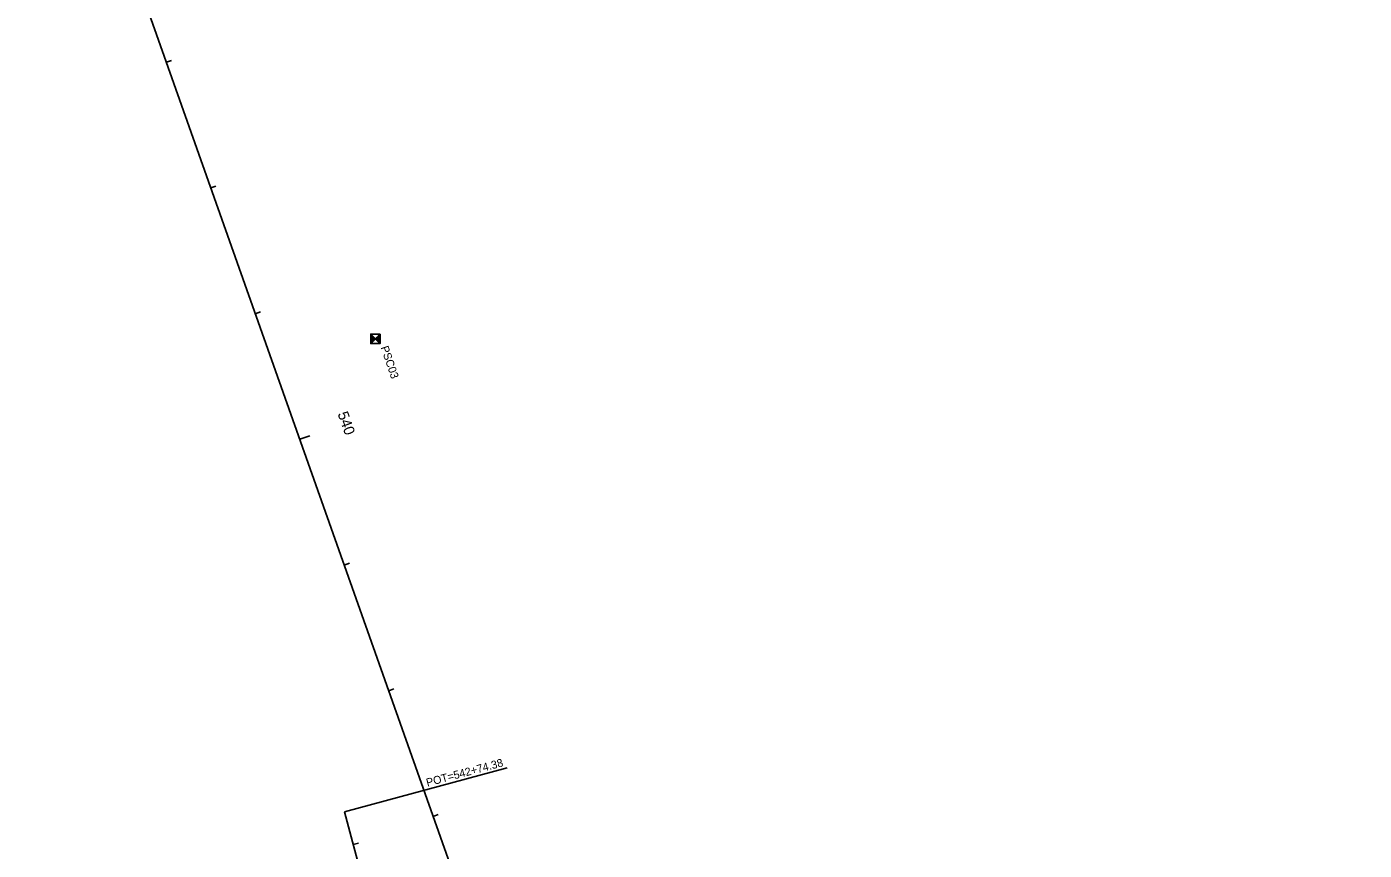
# Model space of a CAD drawing. Extents: x 2004390 to 2008791, y 1133870 to 1140084.
# Drawn here: x 2005036 to 2006039, y 1138747 to 1139364 of the extents above; entities that cross this region are included whole.
import ezdxf

# ---------------------------------------------------------------- set-up
doc = ezdxf.new("R2010")
doc.units = 0
for name, color, linetype in [('RD_HC_Cl', 7, 'Continuous'), ('RD_HC_Data', 7, 'Continuous'), ('RD_HC_Data_Tic', 7, 'Continuous'), ('RD_HC_Survey', 7, 'Continuous'), ('RD_HC_Survey_txCode', 7, 'Continuous'), ('RD_HC_TX_Sta50', 7, 'Continuous')]:
    doc.layers.add(name, color=color, linetype=linetype)

msp = doc.modelspace()

# ---------------------------------------------------------------- linework, layer by layer
at = {"layer": 'RD_HC_Cl'}
for p, q in [((2005036.1, 1139633.5), (2007075.2, 1133869.8)), ((2005274.3, 1138775.6), (2005410.4, 1138267.8))]:
    msp.add_line(p, q, dxfattribs=at)
at = {"layer": 'RD_HC_Data'}
msp.add_line((2005274.3, 1138775.6), (2005396.4, 1138808.4), dxfattribs=at)
at = {"layer": 'RD_HC_Data_Tic'}
for p, q in [((2005140.8, 1139337.7), (2005144.6, 1139339)), ((2005174.2, 1139243.4), (2005177.9, 1139244.8)), ((2005207.5, 1139149.1), (2005211.3, 1139150.5)), ((2005240.9, 1139054.9), (2005248.4, 1139057.5)), ((2005274.2, 1138960.6), (2005278, 1138961.9)), ((2005307.6, 1138866.3), (2005311.3, 1138867.7)), ((2005340.9, 1138772), (2005344.7, 1138773.4)), ((2005280.9, 1138750.9), (2005284.8, 1138751.9))]:
    msp.add_line(p, q, dxfattribs=at)
at = {"layer": 'RD_HC_Survey'}
for p, q in [((2005294, 1139133.8), (2005301.1, 1139126.7)), ((2005301.1, 1139133.8), (2005294, 1139126.7)), ((2005294.1, 1139133.7), (2005294.1, 1139126.7)), ((2005294.1, 1139133.7), (2005294.1, 1139126.8)), ((2005294.2, 1139133.6), (2005294.2, 1139126.8)), ((2005294.2, 1139133.6), (2005294.2, 1139126.9)), ((2005294.3, 1139133.5), (2005294.3, 1139126.9)), ((2005294.3, 1139133.5), (2005294.3, 1139127)), ((2005294.4, 1139133.4), (2005294.4, 1139127)), ((2005294.4, 1139133.4), (2005294.4, 1139127.1)), ((2005294.5, 1139133.3), (2005294.5, 1139127.1)), ((2005294.5, 1139133.3), (2005294.5, 1139127.2)), ((2005294.6, 1139133.2), (2005294.6, 1139127.2)), ((2005294.6, 1139133.2), (2005294.6, 1139127.3)), ((2005294.7, 1139133.1), (2005294.7, 1139127.3)), ((2005294.7, 1139133.1), (2005294.7, 1139127.4)), ((2005294.8, 1139133), (2005294.8, 1139127.4)), ((2005294.8, 1139133), (2005294.8, 1139127.5)), ((2005294.9, 1139132.9), (2005294.9, 1139127.5)), ((2005294.9, 1139132.9), (2005294.9, 1139127.6)), ((2005295, 1139132.8), (2005295, 1139127.6)), ((2005295, 1139132.8), (2005295, 1139127.7)), ((2005295.1, 1139132.7), (2005295.1, 1139127.7)), ((2005295.1, 1139132.7), (2005295.1, 1139127.8)), ((2005295.2, 1139132.6), (2005295.2, 1139127.8)), ((2005295.2, 1139132.6), (2005295.2, 1139127.9)), ((2005295.3, 1139132.5), (2005295.3, 1139127.9)), ((2005295.3, 1139132.5), (2005295.3, 1139128)), ((2005295.4, 1139132.4), (2005295.4, 1139128)), ((2005295.4, 1139132.4), (2005295.4, 1139128.1)), ((2005295.5, 1139132.3), (2005295.5, 1139128.1)), ((2005295.5, 1139132.3), (2005295.5, 1139128.2)), ((2005295.6, 1139132.2), (2005295.6, 1139128.2)), ((2005295.6, 1139132.2), (2005295.6, 1139128.3)), ((2005295.7, 1139132.1), (2005295.7, 1139128.3)), ((2005295.7, 1139132.1), (2005295.7, 1139128.4)), ((2005295.8, 1139132), (2005295.8, 1139128.4)), ((2005295.8, 1139132), (2005295.8, 1139128.5)), ((2005295.9, 1139131.9), (2005295.9, 1139128.5)), ((2005295.9, 1139131.9), (2005295.9, 1139128.6)), ((2005296, 1139131.8), (2005296, 1139128.6)), ((2005296, 1139131.8), (2005296, 1139128.7)), ((2005296.1, 1139131.7), (2005296.1, 1139128.7)), ((2005296.1, 1139131.7), (2005296.1, 1139128.8)), ((2005296.2, 1139131.6), (2005296.2, 1139128.8)), ((2005296.2, 1139131.6), (2005296.2, 1139128.9)), ((2005296.3, 1139131.5), (2005296.3, 1139128.9)), ((2005296.3, 1139131.5), (2005296.3, 1139129)), ((2005296.4, 1139131.4), (2005296.4, 1139129)), ((2005296.4, 1139131.4), (2005296.4, 1139129.1)), ((2005298.7, 1139131.4), (2005298.7, 1139129)), ((2005298.7, 1139131.4), (2005298.7, 1139129.1)), ((2005298.8, 1139131.5), (2005298.8, 1139128.9)), ((2005298.8, 1139131.5), (2005298.8, 1139129)), ((2005298.9, 1139131.6), (2005298.9, 1139128.8)), ((2005298.9, 1139131.6), (2005298.9, 1139128.9)), ((2005299, 1139131.7), (2005299, 1139128.7)), ((2005299, 1139131.7), (2005299, 1139128.8)), ((2005299.1, 1139131.8), (2005299.1, 1139128.6)), ((2005299.1, 1139131.8), (2005299.1, 1139128.7)), ((2005299.2, 1139131.9), (2005299.2, 1139128.5)), ((2005299.2, 1139131.9), (2005299.2, 1139128.6)), ((2005299.3, 1139132), (2005299.3, 1139128.4)), ((2005299.3, 1139132), (2005299.3, 1139128.5)), ((2005299.4, 1139132.1), (2005299.4, 1139128.3)), ((2005299.4, 1139132.1), (2005299.4, 1139128.4)), ((2005299.5, 1139132.2), (2005299.5, 1139128.2)), ((2005299.5, 1139132.2), (2005299.5, 1139128.3)), ((2005299.6, 1139132.3), (2005299.6, 1139128.1)), ((2005299.6, 1139132.3), (2005299.6, 1139128.2)), ((2005299.7, 1139132.4), (2005299.7, 1139128)), ((2005299.7, 1139132.4), (2005299.7, 1139128.1)), ((2005299.8, 1139132.5), (2005299.8, 1139127.9)), ((2005299.8, 1139132.5), (2005299.8, 1139128)), ((2005299.9, 1139132.6), (2005299.9, 1139127.8)), ((2005299.9, 1139132.6), (2005299.9, 1139127.9)), ((2005300, 1139132.7), (2005300, 1139127.7)), ((2005300, 1139132.7), (2005300, 1139127.8)), ((2005300.1, 1139132.8), (2005300.1, 1139127.6)), ((2005300.1, 1139132.8), (2005300.1, 1139127.7)), ((2005300.2, 1139132.9), (2005300.2, 1139127.5)), ((2005300.2, 1139132.9), (2005300.2, 1139127.6)), ((2005300.3, 1139133), (2005300.3, 1139127.4)), ((2005300.3, 1139133), (2005300.3, 1139127.5)), ((2005300.4, 1139133.1), (2005300.4, 1139127.3)), ((2005300.4, 1139133.1), (2005300.4, 1139127.4)), ((2005300.5, 1139133.2), (2005300.5, 1139127.2)), ((2005300.5, 1139133.2), (2005300.5, 1139127.3)), ((2005300.6, 1139133.3), (2005300.6, 1139127.1)), ((2005300.6, 1139133.3), (2005300.6, 1139127.2)), ((2005300.7, 1139133.4), (2005300.7, 1139127)), ((2005300.7, 1139133.4), (2005300.7, 1139127.1)), ((2005300.8, 1139133.5), (2005300.8, 1139126.9)), ((2005300.8, 1139133.5), (2005300.8, 1139127)), ((2005300.9, 1139133.6), (2005300.9, 1139126.8)), ((2005300.9, 1139133.6), (2005300.9, 1139126.9)), ((2005301, 1139133.7), (2005301, 1139126.7)), ((2005301, 1139133.7), (2005301, 1139126.8)), ((2005296.5, 1139131.3), (2005296.5, 1139129.1)), ((2005296.5, 1139131.3), (2005296.5, 1139129.2)), ((2005296.6, 1139131.2), (2005296.6, 1139129.2)), ((2005296.6, 1139131.2), (2005296.6, 1139129.3)), ((2005296.7, 1139131.1), (2005296.7, 1139129.3)), ((2005296.7, 1139131.1), (2005296.7, 1139129.4)), ((2005296.8, 1139131), (2005296.8, 1139129.4)), ((2005296.8, 1139131), (2005296.8, 1139129.5)), ((2005296.9, 1139130.9), (2005296.9, 1139129.5)), ((2005296.9, 1139130.9), (2005296.9, 1139129.6)), ((2005297, 1139130.8), (2005297, 1139129.6)), ((2005297, 1139130.8), (2005297, 1139129.7)), ((2005297.1, 1139130.7), (2005297.1, 1139129.7)), ((2005297.1, 1139130.7), (2005297.1, 1139129.8)), ((2005297.2, 1139130.6), (2005297.2, 1139129.8)), ((2005297.2, 1139130.6), (2005297.2, 1139129.9)), ((2005297.3, 1139130.5), (2005297.3, 1139129.9)), ((2005297.3, 1139130.5), (2005297.3, 1139130)), ((2005297.4, 1139130.4), (2005297.4, 1139130)), ((2005297.4, 1139130.4), (2005297.4, 1139130.1)), ((2005297.5, 1139130.3), (2005297.5, 1139130.1)), ((2005297.5, 1139130.3), (2005297.5, 1139130.2)), ((2005297.6, 1139130.3), (2005297.6, 1139130.1)), ((2005297.6, 1139130.3), (2005297.6, 1139130.2)), ((2005297.7, 1139130.4), (2005297.7, 1139130)), ((2005297.7, 1139130.4), (2005297.7, 1139130.1)), ((2005297.8, 1139130.5), (2005297.8, 1139129.9)), ((2005297.8, 1139130.5), (2005297.8, 1139130)), ((2005297.9, 1139130.6), (2005297.9, 1139129.8)), ((2005297.9, 1139130.6), (2005297.9, 1139129.9)), ((2005298, 1139130.7), (2005298, 1139129.7)), ((2005298, 1139130.7), (2005298, 1139129.8)), ((2005298.1, 1139130.8), (2005298.1, 1139129.6)), ((2005298.1, 1139130.8), (2005298.1, 1139129.7)), ((2005298.2, 1139130.9), (2005298.2, 1139129.5)), ((2005298.2, 1139130.9), (2005298.2, 1139129.6)), ((2005298.3, 1139131), (2005298.3, 1139129.4)), ((2005298.3, 1139131), (2005298.3, 1139129.5)), ((2005298.4, 1139131.1), (2005298.4, 1139129.3)), ((2005298.4, 1139131.1), (2005298.4, 1139129.4)), ((2005298.5, 1139131.2), (2005298.5, 1139129.2)), ((2005298.5, 1139131.2), (2005298.5, 1139129.3)), ((2005298.6, 1139131.3), (2005298.6, 1139129.1)), ((2005298.6, 1139131.3), (2005298.6, 1139129.2))]:
    msp.add_line(p, q, dxfattribs=at)
msp.add_lwpolyline([(2005301.1, 1139133.8), (2005294, 1139133.8), (2005294, 1139126.7), (2005301.1, 1139126.7)], close=True, dxfattribs=at)

# ---------------------------------------------------------------- texts
at = {"layer": 'RD_HC_Data'}
msp.add_text('POT=542+74.38', height=6, rotation=15.0109, dxfattribs=at).set_placement((2005336.5, 1138794.4))
at = {"layer": 'RD_HC_Survey_txCode'}
msp.add_text('PSC03', height=6, rotation=288.8025, dxfattribs=at).set_placement((2005301.4, 1139123.8))
at = {"layer": 'RD_HC_TX_Sta50'}
msp.add_text('540', height=8, rotation=289.482, dxfattribs=at).set_placement((2005269.1, 1139074.1))

doc.saveas('drawing.dxf')
